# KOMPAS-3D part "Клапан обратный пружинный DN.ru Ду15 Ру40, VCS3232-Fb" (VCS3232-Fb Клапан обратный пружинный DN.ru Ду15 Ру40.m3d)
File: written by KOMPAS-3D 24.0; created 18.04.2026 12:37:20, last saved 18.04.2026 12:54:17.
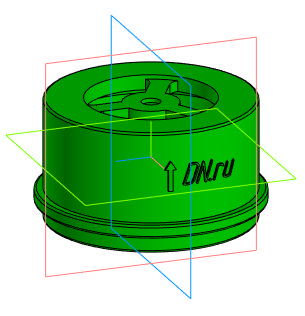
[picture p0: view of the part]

Document properties: Автор: 712; Полное имя файла: C:\Users\712\Desktop\Новая папка (4)\VCS3232-Fb Клапан обратный пружинный DN.ru Ду15 Ру40.m3d

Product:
- Body: Тело 1  | qty 1
    Масса: 0.17889
- Part/product: Клапан обратный пружинный DN.ru Ду15 Ру40  | designation VCS3232-Fb
    Масса: 0.16
    Раздел спецификации: Прочие изделия
    Примечание: D100-03904
    additional columns: 071bd168-1a06-425c-849c-e99e84a96128; Деталь; 712; c; Шероховатость не задана; Да

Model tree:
1. Операция без истории:2

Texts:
  VCS3232-Fb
